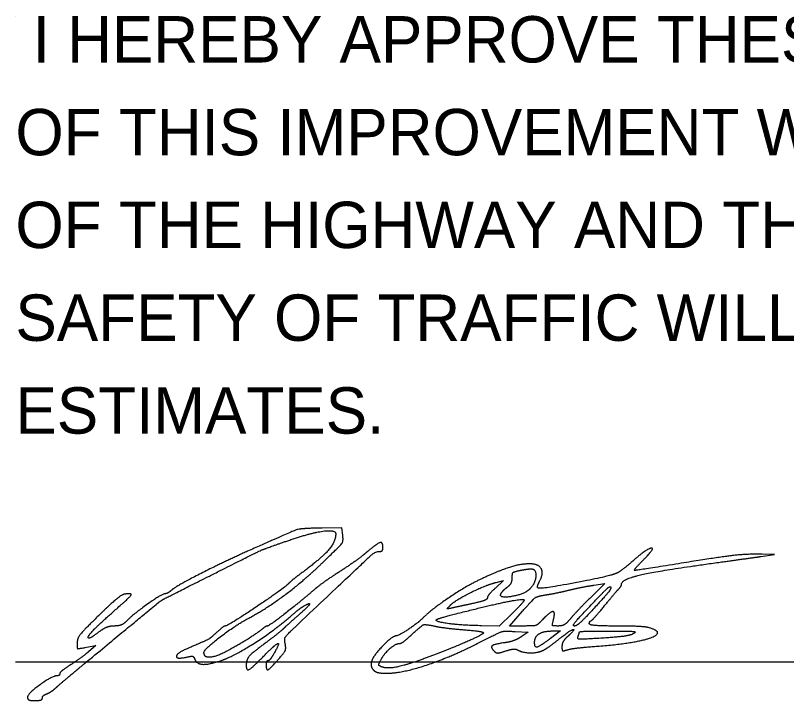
# Model space of a CAD drawing. Extents: x 0 to 34, y 0 to 22.
# Drawn here: x 24.528 to 26.854, y 8.809 to 10.877 of the extents above; entities that cross this region are included whole.
import ezdxf

# ---------------------------------------------------------------- set-up
doc = ezdxf.new("R2010")
doc.units = 0
doc.layers.add('SH_Data', color=7, linetype='Continuous')
doc.layers.add('SH_Text', color=7, linetype='Continuous')

msp = doc.modelspace()

# ---------------------------------------------------------------- linework, layer by layer
at = {"layer": 'SH_Data'}
for p, q in [((24.5279, 10.875), (24.5279, 10.875)), ((24.5279, 8.9262), (28.0279, 8.9262))]:
    msp.add_line(p, q, dxfattribs=at)
at = {"layer": 'SH_Text'}
msp.add_line((24.5642, 8.8197), (24.5642, 8.8197), dxfattribs=at)
for points in [[(25.5155, 9.3089), (25.513, 9.3307), (25.453, 9.33)], [(26.7767, 9.2442), (26.818, 9.25), (26.7803, 9.251)], [(25.9781, 9.1661), (26.0005, 9.1714), (25.9761, 9.1492)], [(26.273, 9.1576), (26.3056, 9.1624), (26.2618, 9.119)], [(26.0592, 9.0345), (26.0183, 9.0345), (26.0576, 9.079)], [(26.0265, 9.0725), (25.9873, 9.0345), (25.9339, 9.0354)], [(26.0358, 9.018), (26.075, 9.0157), (26.0536, 9.0017)], [(26.1468, 9.0195), (26.1719, 9.0195), (26.1424, 8.9972)], [(24.7424, 8.9703), (24.7705, 8.9752), (24.748, 8.9564)]]:
    msp.add_lwpolyline(points, dxfattribs=at)
for points in [[(25.453, 9.33), (25.3905, 9.3293), (25.3641, 9.3211), (25.228, 9.26)], [(25.3555, 9.294), (25.4195, 9.3158), (25.4942, 9.3258), (25.4942, 9.3125)], [(25.4942, 9.3125), (25.4942, 9.2886), (25.4492, 9.2372), (25.3901, 9.1937)], [(25.4554, 9.2264), (25.5094, 9.2788), (25.5176, 9.29), (25.5155, 9.3089)], [(25.1455, 9.2017), (25.2577, 9.2581), (25.2833, 9.2693), (25.3555, 9.294)], [(25.6367, 9.2707), (25.6367, 9.2887), (25.6192, 9.2838), (25.5875, 9.257)], [(25.228, 9.26), (25.1478, 9.2239), (25.0119, 9.1544), (24.9986, 9.1425)], [(25.6274, 9.2595), (25.6325, 9.2595), (25.6367, 9.2645), (25.6367, 9.2707)], [(26.4235, 9.2351), (26.4603, 9.2719), (26.4308, 9.2666), (26.3879, 9.2286)], [(25.3704, 9.0303), (25.5918, 9.2399), (25.6137, 9.2594), (25.6274, 9.2595)], [(25.5875, 9.257), (25.5712, 9.2433), (25.5344, 9.2169), (25.5055, 9.1982)], [(26.7803, 9.251), (26.7359, 9.2521), (26.6519, 9.2425), (26.5203, 9.2212)], [(26.65, 9.2266), (26.697, 9.2331), (26.754, 9.241), (26.7767, 9.2442)], [(25.2321, 9.0585), (25.2858, 9.0869), (25.4005, 9.1731), (25.4554, 9.2264)], [(26.0793, 9.222), (26.0518, 9.222), (25.99, 9.2028), (25.9346, 9.1771)], [(26.1094, 9.1698), (26.1222, 9.1937), (26.1059, 9.222), (26.0793, 9.222)], [(26.3879, 9.2286), (26.3687, 9.2117), (26.3462, 9.1953), (26.338, 9.1923)], [(26.3567, 9.1616), (26.3567, 9.176), (26.4793, 9.2032), (26.65, 9.2266)], [(26.5203, 9.2212), (26.3999, 9.2016), (26.3913, 9.2029), (26.4235, 9.2351)], [(24.7367, 8.9215), (24.9613, 9.1075), (24.9709, 9.114), (25.1455, 9.2017)], [(25.3901, 9.1937), (25.3752, 9.1828), (25.357, 9.1678), (25.3498, 9.1606)], [(25.5055, 9.1982), (25.4766, 9.1796), (25.4429, 9.1556), (25.4305, 9.145)], [(26.0267, 9.1802), (26.0267, 9.1937), (26.032, 9.1986), (26.0502, 9.2023)], [(26.0502, 9.2023), (26.0631, 9.2049), (26.0782, 9.207), (26.0839, 9.207)], [(26.0839, 9.207), (26.0989, 9.207), (26.0969, 9.1642), (26.0811, 9.1475)], [(26.338, 9.1923), (26.3106, 9.1822), (26.1089, 9.1448), (26.1047, 9.149)], [(25.9346, 9.1771), (25.8925, 9.1577), (25.784, 9.0854), (25.7583, 9.0596)], [(26.0131, 9.153), (26.0206, 9.1584), (26.0267, 9.1706), (26.0267, 9.1802)], [(26.1047, 9.149), (26.1024, 9.1513), (26.1045, 9.1606), (26.1094, 9.1698)], [(25.3498, 9.1606), (25.3349, 9.1458), (25.1682, 9.0345), (25.1608, 9.0345)], [(25.4305, 9.145), (25.3858, 9.1066), (25.2931, 9.0345), (25.2884, 9.0345)], [(25.8392, 9.0967), (25.8536, 9.1116), (25.9487, 9.1591), (25.9781, 9.1661)], [(25.9761, 9.1492), (25.9627, 9.1369), (25.9517, 9.1235), (25.9517, 9.1194)], [(26.0811, 9.1475), (26.0647, 9.1302), (25.9837, 9.1168), (25.9934, 9.133)], [(25.9934, 9.133), (25.9968, 9.1386), (26.0057, 9.1476), (26.0131, 9.153)], [(26.1992, 9.1431), (26.2219, 9.1485), (26.2551, 9.155), (26.273, 9.1576)], [(26.3237, 9.1525), (26.3272, 9.149), (26.3034, 9.12), (26.2507, 9.0636)], [(26.2991, 9.1339), (26.3107, 9.146), (26.3218, 9.1544), (26.3237, 9.1525)], [(26.3042, 9.0945), (26.3227, 9.1172), (26.3421, 9.1402), (26.3473, 9.1456)], [(26.3473, 9.1456), (26.3525, 9.1511), (26.3567, 9.1583), (26.3567, 9.1616)], [(24.8571, 9.1306), (24.849, 9.1293), (24.8136, 9.0999), (24.7783, 9.0654)], [(24.8474, 9.0991), (24.8751, 9.1232), (24.8784, 9.1341), (24.8571, 9.1306)], [(24.9795, 9.132), (24.9708, 9.132), (24.8811, 9.0682), (24.8621, 9.0484)], [(24.9986, 9.1425), (24.9921, 9.1367), (24.9835, 9.132), (24.9795, 9.132)], [(26.0576, 9.079), (26.0899, 9.1158), (26.1021, 9.1244), (26.1274, 9.1284)], [(26.1274, 9.1284), (26.1442, 9.1311), (26.1765, 9.1377), (26.1992, 9.1431)], [(26.2146, 9.0345), (26.2067, 9.0345), (26.2281, 9.0597), (26.2991, 9.1339)], [(24.7473, 8.9988), (24.7437, 9.0025), (24.7906, 9.0495), (24.8474, 9.0991)], [(25.3995, 9.0956), (25.4203, 9.1072), (25.4077, 9.0895), (25.3751, 9.0612)], [(25.8467, 9.0891), (25.8299, 9.0855), (25.8291, 9.0863), (25.8392, 9.0967)], [(25.9086, 9.1025), (25.8849, 9.0974), (25.857, 9.0914), (25.8467, 9.0891)], [(25.852, 9.0701), (25.9488, 9.0949), (26.0584, 9.1178), (26.0622, 9.114)], [(25.9517, 9.1194), (25.9517, 9.1152), (25.9323, 9.1077), (25.9086, 9.1025)], [(26.0622, 9.114), (26.0641, 9.1121), (26.0481, 9.0934), (26.0265, 9.0725)], [(26.2618, 9.119), (26.2377, 9.0952), (26.2104, 9.0664), (26.2012, 9.0551)], [(25.3592, 9.0647), (25.3737, 9.0774), (25.3918, 9.0913), (25.3995, 9.0956)], [(26.1511, 9.0532), (26.1574, 9.078), (26.1413, 9.0779), (26.1178, 9.0531)], [(26.2649, 9.0507), (26.2679, 9.0521), (26.2856, 9.0718), (26.3042, 9.0945)], [(24.7783, 9.0654), (24.732, 9.0199), (24.7142, 8.9974), (24.7142, 8.9839)], [(25.0967, 8.9545), (25.0967, 8.964), (25.1925, 9.0376), (25.2321, 9.0585)], [(25.15, 8.9308), (25.187, 8.9435), (25.3136, 9.0245), (25.3592, 9.0647)], [(25.3751, 9.0612), (25.3605, 9.0486), (25.3429, 9.0327), (25.336, 9.026)], [(25.7583, 9.0596), (25.743, 9.0443), (25.6837, 9.0045), (25.6763, 9.0045)], [(25.7971, 9.0515), (25.7952, 9.0535), (25.8199, 9.0619), (25.852, 9.0701)], [(25.9339, 9.0354), (25.8786, 9.0364), (25.8034, 9.0452), (25.7971, 9.0515)], [(26.1178, 9.0531), (26.1032, 9.0377), (26.0931, 9.0345), (26.0592, 9.0345)], [(26.1654, 9.0345), (26.1489, 9.0345), (26.1471, 9.0369), (26.1511, 9.0532)], [(26.2012, 9.0551), (26.1909, 9.0425), (26.177, 9.0345), (26.1654, 9.0345)], [(26.2507, 9.0636), (26.2357, 9.0476), (26.2195, 9.0345), (26.2146, 9.0345)], [(26.2592, 9.0413), (26.2592, 9.0451), (26.2618, 9.0493), (26.2649, 9.0507)], [(24.8259, 9.0345), (24.8129, 9.0345), (24.7921, 9.026), (24.7773, 9.0147)], [(24.8621, 9.0484), (24.8547, 9.0407), (24.8384, 9.0345), (24.8259, 9.0345)], [(25.1608, 9.0345), (25.1582, 9.0345), (25.147, 9.026), (25.1359, 9.0157)], [(25.2745, 9.0269), (25.2599, 9.0146), (25.2121, 8.9841), (25.1753, 8.9635)], [(25.2884, 9.0345), (25.2858, 9.0345), (25.2795, 9.031), (25.2745, 9.0269)], [(25.3419, 8.9807), (25.339, 8.996), (25.3448, 9.0061), (25.3704, 9.0303)], [(25.7084, 8.9952), (25.7526, 9.0354), (25.7635, 9.0405), (25.7923, 9.0343)], [(25.7923, 9.0343), (25.8078, 9.031), (25.8486, 9.0259), (25.883, 9.023)], [(26.3399, 9.0344), (26.2955, 9.0344), (26.2592, 9.0376), (26.2592, 9.0413)], [(26.2892, 8.9741), (26.4005, 8.9827), (26.4891, 9.0159), (26.4377, 9.0297)], [(26.4377, 9.0297), (26.4282, 9.0322), (26.3842, 9.0343), (26.3399, 9.0344)], [(24.7773, 9.0147), (24.763, 9.0038), (24.7495, 8.9967), (24.7473, 8.9988)], [(25.1359, 9.0157), (25.1166, 8.9979), (25.1022, 8.9899), (25.0461, 8.9661)], [(25.336, 9.026), (25.3292, 9.0193), (25.3047, 8.9998), (25.2816, 8.9828)], [(25.6763, 9.0045), (25.6653, 9.0045), (25.6082, 8.946), (25.603, 8.9294)], [(25.9393, 9.0124), (25.9298, 9.0043), (25.8278, 8.9605), (25.7642, 8.9371)], [(25.883, 9.023), (25.9174, 9.0202), (25.9427, 9.0154), (25.9393, 9.0124)], [(25.9535, 8.9978), (25.9884, 9.016), (26.004, 9.0198), (26.0358, 9.018)], [(26.0942, 8.9846), (26.0942, 9.0019), (26.1206, 9.0195), (26.1468, 9.0195)], [(26.1678, 8.995), (26.2004, 9.0214), (26.2196, 9.026), (26.1918, 9.0008)], [(26.2254, 9.0031), (26.2275, 9.0087), (26.2292, 9.0146), (26.2292, 9.0163)], [(26.2292, 9.0163), (26.2292, 9.0181), (26.2689, 9.0194), (26.3174, 9.0192)], [(26.3915, 9.0109), (26.3838, 9.0064), (26.3424, 9.0006), (26.2995, 8.9979)], [(26.3174, 9.0192), (26.3844, 9.0191), (26.4021, 9.0171), (26.3915, 9.0109)], [(24.7142, 8.9839), (24.7142, 8.9665), (24.7161, 8.9656), (24.7424, 8.9703)], [(25.2816, 8.9828), (25.2417, 8.9533), (25.2242, 8.9326), (25.2242, 8.915)], [(25.2742, 8.9407), (25.3125, 8.9797), (25.3266, 8.9843), (25.3083, 8.952)], [(25.3216, 8.9342), (25.3393, 8.9544), (25.3446, 8.9666), (25.3419, 8.9807)], [(25.6302, 8.9319), (25.6399, 8.9507), (25.6742, 8.9813), (25.6859, 8.9817)], [(25.6473, 8.892), (25.6969, 8.892), (25.8562, 8.947), (25.9535, 8.9978)], [(25.6859, 8.9817), (25.6903, 8.9818), (25.7004, 8.9879), (25.7084, 8.9952)], [(26.003, 8.9839), (25.9716, 8.9796), (25.9605, 8.9702), (25.9727, 8.958)], [(26.0536, 9.0017), (26.0418, 8.9941), (26.019, 8.986), (26.003, 8.9839)], [(26.1424, 8.9972), (26.1104, 8.973), (26.0942, 8.9687), (26.0942, 8.9846)], [(26.1205, 8.9614), (26.1287, 8.9655), (26.15, 8.9807), (26.1678, 8.995)], [(26.1918, 9.0008), (26.1835, 8.9933), (26.1767, 8.9805), (26.1767, 8.9724)], [(26.2995, 8.9979), (26.2359, 8.994), (26.2222, 8.9949), (26.2254, 9.0031)], [(25.0461, 8.9661), (25.0149, 8.9529), (25.0127, 8.9338), (25.0433, 8.9405)], [(25.1753, 8.9635), (25.1382, 8.9428), (25.0967, 8.938), (25.0967, 8.9545)], [(25.9727, 8.958), (25.9779, 8.9528), (25.9889, 8.9532), (26.0071, 8.9592)], [(26.0071, 8.9592), (26.0219, 8.9641), (26.0378, 8.9656), (26.0426, 8.9627)], [(26.0426, 8.9627), (26.0567, 8.954), (26.1043, 8.9532), (26.1205, 8.9614)], [(26.1767, 8.9724), (26.1767, 8.9606), (26.1801, 8.9587), (26.1936, 8.9629)], [(26.1936, 8.9629), (26.2029, 8.9657), (26.2459, 8.9708), (26.2892, 8.9741)], [(24.748, 8.9564), (24.7356, 8.946), (24.7111, 8.9283), (24.6936, 8.917)], [(25.0433, 8.9405), (25.059, 8.944), (25.066, 8.9421), (25.0693, 8.9336)], [(25.2242, 8.915), (25.2242, 8.8988), (25.2417, 8.9078), (25.2742, 8.9407)], [(25.2842, 8.9182), (25.2842, 8.9), (25.296, 8.9051), (25.3216, 8.9342)], [(25.3083, 8.952), (25.3012, 8.9397), (25.2929, 8.9295), (25.2899, 8.9295)], [(25.7642, 8.9371), (25.7069, 8.9161), (25.6479, 8.9049), (25.6312, 8.9118)], [(24.6542, 8.8517), (24.6645, 8.8611), (24.7017, 8.8925), (24.7367, 8.9215)], [(24.6936, 8.917), (24.6761, 8.9057), (24.6617, 8.8938), (24.6617, 8.8905)], [(25.0693, 8.9336), (25.0747, 8.9195), (25.1135, 8.9182), (25.15, 8.9308)], [(25.2899, 8.9295), (25.2868, 8.9295), (25.2842, 8.9244), (25.2842, 8.9182)], [(25.603, 8.9294), (25.6002, 8.9208), (25.602, 8.9089), (25.607, 8.9029)], [(25.6312, 8.9118), (25.6241, 8.9148), (25.6239, 8.9196), (25.6302, 8.9319)], [(24.6617, 8.8905), (24.6617, 8.8872), (24.6583, 8.8845), (24.6541, 8.8845)], [(25.607, 8.9029), (25.6123, 8.8965), (25.6291, 8.892), (25.6473, 8.892)], [(24.6541, 8.8845), (24.6399, 8.8845), (24.5642, 8.8299), (24.5642, 8.8197)], [(24.6224, 8.8298), (24.6296, 8.8325), (24.6439, 8.8424), (24.6542, 8.8517)], [(24.5642, 8.8197), (24.5642, 8.8133), (24.5728, 8.8095), (24.5867, 8.8095)], [(24.6092, 8.8172), (24.6092, 8.8215), (24.6151, 8.8271), (24.6224, 8.8298)], [(24.5867, 8.8095), (24.5991, 8.8095), (24.6092, 8.8129), (24.6092, 8.8172)]]:
    msp.add_open_spline(points, degree=2, dxfattribs=at)

# ---------------------------------------------------------------- texts
at = {"layer": 'SH_Data'}
for s, p in [(' I HEREBY APPROVE THESE PLANS AND DECLARE THAT THE MAKING ', (24.5279, 10.735)), ('OF THIS IMPROVEMENT WILL NOT REQUIRE THE CLOSING TO TRAFFIC ', (24.5279, 10.455)), ('OF THE HIGHWAY AND THAT PROVISIONS FOR THEMAINTENANCE AND ', (24.5279, 10.175)), ('SAFETY OF TRAFFIC WILL BE AS SET FORTH ON THE PLANS AND ', (24.5279, 9.895)), ('ESTIMATES.', (24.5279, 9.615))]:
    msp.add_text(s, height=0.14, dxfattribs=at).set_placement(p)

doc.saveas('drawing.dxf')
